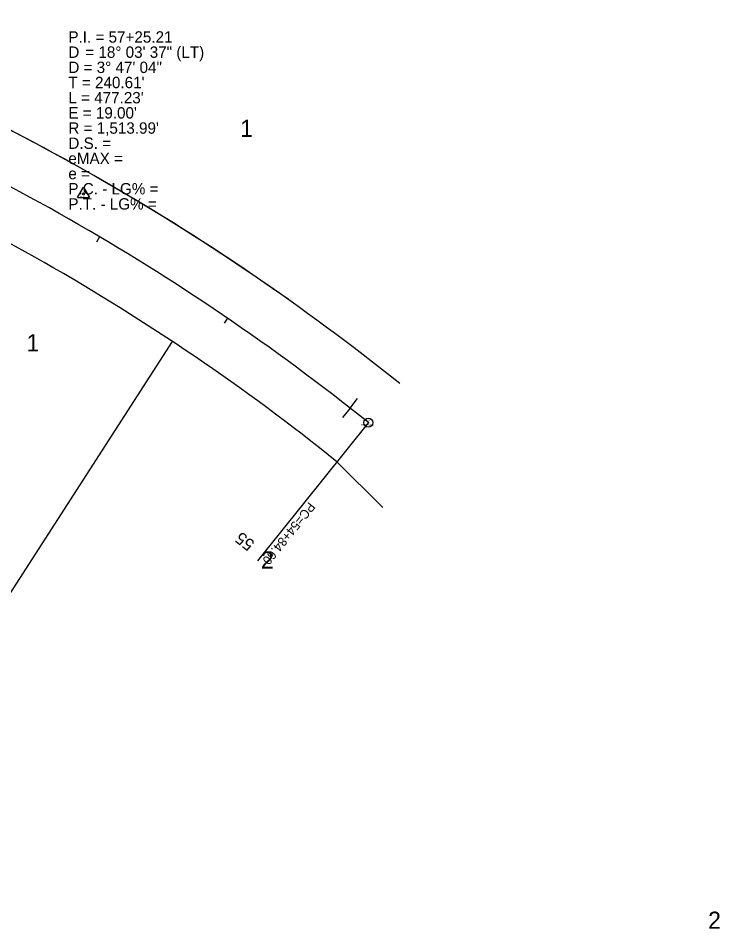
# Model space of a CAD drawing. Extents: x 2519952 to 2531965, y 848341 to 887632.
# Drawn here: x 2523377 to 2523839, y 863123 to 863723 of the extents above; entities that cross this region are included whole.
import ezdxf

# ---------------------------------------------------------------- set-up
doc = ezdxf.new("R2010")
doc.units = 0
for name, color, linetype in [('RD_EX_DV_Prop', 7, 'Continuous'), ('RD_EX_DV_TX_Prop', 7, 'Continuous'), ('RD_EX_RW', 7, 'Continuous'), ('RD_HC_Cl', 7, 'Continuous'), ('RD_HC_Data', 7, 'Continuous'), ('RD_HC_Data_Tic', 7, 'Continuous'), ('RD_HC_Survey_txCode', 7, 'Continuous'), ('RD_HC_TX_Sta50', 7, 'Continuous'), ('RD_HC_txCode', 7, 'Continuous'), ('RD_SMD_Locator', 7, 'Continuous')]:
    doc.layers.add(name, color=color, linetype=linetype)

msp = doc.modelspace()

# ---------------------------------------------------------------- linework, layer by layer
at = {"layer": 'RD_EX_DV_Prop'}
for p, q in [((2523353.97, 863315.62), (2523479.02, 863509.55)), ((2523587.29, 863430.45), (2523617.49, 863400.2))]:
    msp.add_line(p, q, dxfattribs=at)
for radius, start, end in [(1546.99, 54.66603, 69.31315), (1480.99, 51.25287, 69.31316)]:
    msp.add_arc((2522660.36, 862275.4), radius, start, end, dxfattribs=at)
at = {"layer": 'RD_EX_RW'}
for radius in [1546.99, 1480.99]:
    msp.add_arc((2522660.36, 862275.4), radius, 51.25288, 69.31313, dxfattribs=at)
at = {"layer": 'RD_HC_Cl'}
msp.add_arc((2522660.36, 862275.4), 1513.99, 51.25288, 69.31313, dxfattribs=at)
at = {"layer": 'RD_HC_Data'}
for p, q in [((2523416.32, 863604.49), (2523420.29, 863611.37)), ((2523420.29, 863611.37), (2523424.26, 863604.49)), ((2523416.32, 863604.49), (2523424.26, 863604.49)), ((2523607.95, 863456.19), (2523534.91, 863365.18))]:
    msp.add_line(p, q, dxfattribs=at)
for centre, radius in [((2523420.29, 863606.78), 0.529), ((2523607.95, 863456.19), 3), ((2523607.95, 863456.19), 0.282)]:
    msp.add_circle(centre, radius, dxfattribs=at)
at = {"layer": 'RD_HC_Data_Tic'}
for p, q in [((2523430.95, 863578.62), (2523428.91, 863575.18)), ((2523515.28, 863524.92), (2523513.02, 863521.62)), ((2523595.89, 863465.77), (2523600.83, 863472.06)), ((2523595.89, 863465.77), (2523590.94, 863459.48))]:
    msp.add_line(p, q, dxfattribs=at)
at = {"layer": 'RD_SMD_Locator'}
for centre in [(2523420.29, 863606.78), (2523607.95, 863456.19)]:
    msp.add_circle(centre, 0.001, dxfattribs=at)

# ---------------------------------------------------------------- texts
at = {"layer": 'RD_EX_DV_TX_Prop'}
for s, p in [('1', (2523523.49, 863644.41)), ('1', (2523382.79, 863503.12)), ('2', (2523537.17, 863359.97)), ('2', (2523831.77, 863122.66))]:
    msp.add_text(s, height=11.32, dxfattribs=at).set_placement(p)
at = {"layer": 'RD_HC_Data'}
msp.add_text('PC=54+84.60', height=6, rotation=231.25288, dxfattribs=at).set_placement((2523568.82, 863404.24))
at = {"layer": 'RD_HC_Survey_txCode'}
for s, p in [('P.I. = 57+25.21', (2523410.36, 863706.54)), ('D', (2523410.36, 863696.54)), ('    = 18%%d 03\' 37" (LT)', (2523410.36, 863696.54)), ('D = 3%%d 47\' 04"', (2523410.36, 863686.54)), ("T = 240.61'", (2523410.36, 863676.54)), ("L = 477.23'", (2523410.36, 863666.54)), ("E = 19.00'", (2523410.36, 863656.54)), ("R = 1,513.99'", (2523410.36, 863646.54)), ('D.S. = ', (2523410.36, 863636.54)), ('eMAX = ', (2523410.36, 863626.54)), ('e = ', (2523410.36, 863616.54)), ('P.C. - LG% = ', (2523410.36, 863606.54)), ('P.T. - LG% = ', (2523410.36, 863596.54))]:
    msp.add_text(s, height=7.5, dxfattribs=at).set_placement(p)
at = {"layer": 'RD_HC_TX_Sta50'}
msp.add_text('55', height=8, rotation=141.83568, dxfattribs=at).set_placement((2523533.68, 863377.29))
at = {"layer": 'RD_HC_txCode'}
for s, p in [('22', (2523419.56, 863607.78)), ('PI 57+21.22', (2523416.51, 863604.78)), ('21', (2523607.5, 863457.19)), ('PC 54+84.60', (2523603.21, 863454.19))]:
    msp.add_text(s, height=1, dxfattribs=at).set_placement(p)

doc.saveas('drawing.dxf')
